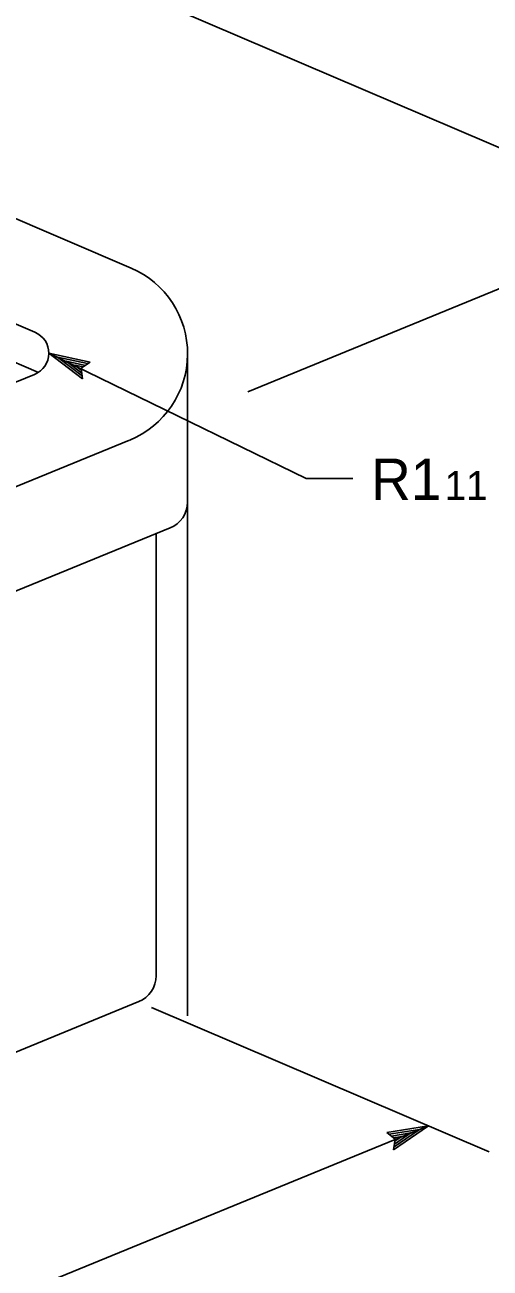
# Model space of a CAD drawing. Extents: x -123486 to -116575, y -107066 to -101122.
# Drawn here: x -116954.3 to -116886.6, y -101489.7 to -101309.2 of the extents above; entities that cross this region are included whole.
import ezdxf

# ---------------------------------------------------------------- set-up
doc = ezdxf.new("R2010")
doc.units = 0
for name, color, linetype in [('G-MARK', 7, 'Continuous'), ('G-TEXT', 7, 'Continuous'), ('Misc CnstDet(22)', 7, 'Continuous')]:
    doc.layers.add(name, color=color, linetype=linetype)

msp = doc.modelspace()

# ---------------------------------------------------------------- linework, layer by layer
at = {"layer": 'G-MARK'}
for p, q in [((-116860.82, -101337.49), (-116981.97, -101285.71)), ((-116855.35, -101335.26), (-116921.86, -101362.45)), ((-116886.75, -101472.87), (-116935.88, -101451.87)), ((-116895.6, -101469.09), (-117047.1, -101531.02))]:
    msp.add_line(p, q, dxfattribs=at)
msp.add_lwpolyline([(-116950.8, -101356.86), (-116913.36, -101375.06), (-116906.61, -101375.06)], dxfattribs=at)
at = {"layer": 'G-TEXT'}
for p, q in [((-116945.91, -101360.58), (-116950.8, -101356.86)), ((-116950.8, -101356.86), (-116950.8, -101356.86)), ((-116950.8, -101356.86), (-116944.79, -101358.16)), ((-116945.96, -101360.17), (-116949.55, -101357.44)), ((-116949.54, -101357.44), (-116945.16, -101358.38)), ((-116946.02, -101359.74), (-116948.29, -101358.01)), ((-116948.29, -101358.01), (-116945.46, -101358.63)), ((-116946.04, -101359.36), (-116947.04, -101358.59)), ((-116947.04, -101358.59), (-116945.83, -101358.85)), ((-116944.79, -101358.16), (-116946.08, -101359.03)), ((-116946.08, -101359.03), (-116945.91, -101360.58)), ((-116944.79, -101358.16), (-116944.79, -101358.16)), ((-116945.91, -101360.58), (-116945.91, -101360.58)), ((-116901.67, -101470.06), (-116895.6, -101469.09)), ((-116895.6, -101469.09), (-116900.68, -101472.54)), ((-116895.6, -101469.09), (-116895.6, -101469.09)), ((-116900.43, -101471.01), (-116901.67, -101470.06)), ((-116901.67, -101470.06), (-116901.67, -101470.06)), ((-116901.33, -101470.31), (-116896.88, -101469.6)), ((-116900.98, -101470.56), (-116898.16, -101470.11)), ((-116900.69, -101470.81), (-116899.45, -101470.62)), ((-116900.68, -101472.54), (-116900.43, -101471.01)), ((-116896.89, -101469.61), (-116900.6, -101472.12)), ((-116898.16, -101470.11), (-116900.56, -101471.73)), ((-116899.45, -101470.62), (-116900.47, -101471.31)), ((-116900.68, -101472.54), (-116900.68, -101472.54))]:
    msp.add_line(p, q, dxfattribs=at)
at = {"layer": 'Misc CnstDet(22)'}
for p, q in [((-117008.88, -101314.56), (-116938.85, -101344.49)), ((-117014.4, -101327.48), (-116952.83, -101353.79)), ((-117016.43, -101332.24), (-116952.31, -101359.65)), ((-116930.63, -101356.94), (-116930.63, -101378.48)), ((-117007.18, -101382.14), (-116952.87, -101359.94)), ((-116989.02, -101389.9), (-116939.05, -101369.47)), ((-116930.63, -101368.37), (-116930.63, -101453.12)), ((-116995.2, -101407.6), (-116933.16, -101382.24)), ((-116935.19, -101383.08), (-116935.19, -101447.27)), ((-116995.2, -101474.53), (-116937.72, -101451.04))]:
    msp.add_line(p, q, dxfattribs=at)
for centre, radius, end in [((-116944.17, -101356.94), 13.54, 66.8572), ((-116954.14, -101356.86), 3.33, 66.8572), ((-116934.7, -101378.48), 4.07, 0), ((-116939.26, -101447.27), 4.07, 0)]:
    msp.add_arc(centre, radius, 292.2327, end, dxfattribs=at)

# ---------------------------------------------------------------- texts
for s, height, p in [('R1', 6, (-116903.96, -101378.17)), ('11', 4.2, (-116893.25, -101378.17))]:
    msp.add_text(s, height=height, dxfattribs=at).set_placement(p)

doc.saveas('drawing.dxf')
